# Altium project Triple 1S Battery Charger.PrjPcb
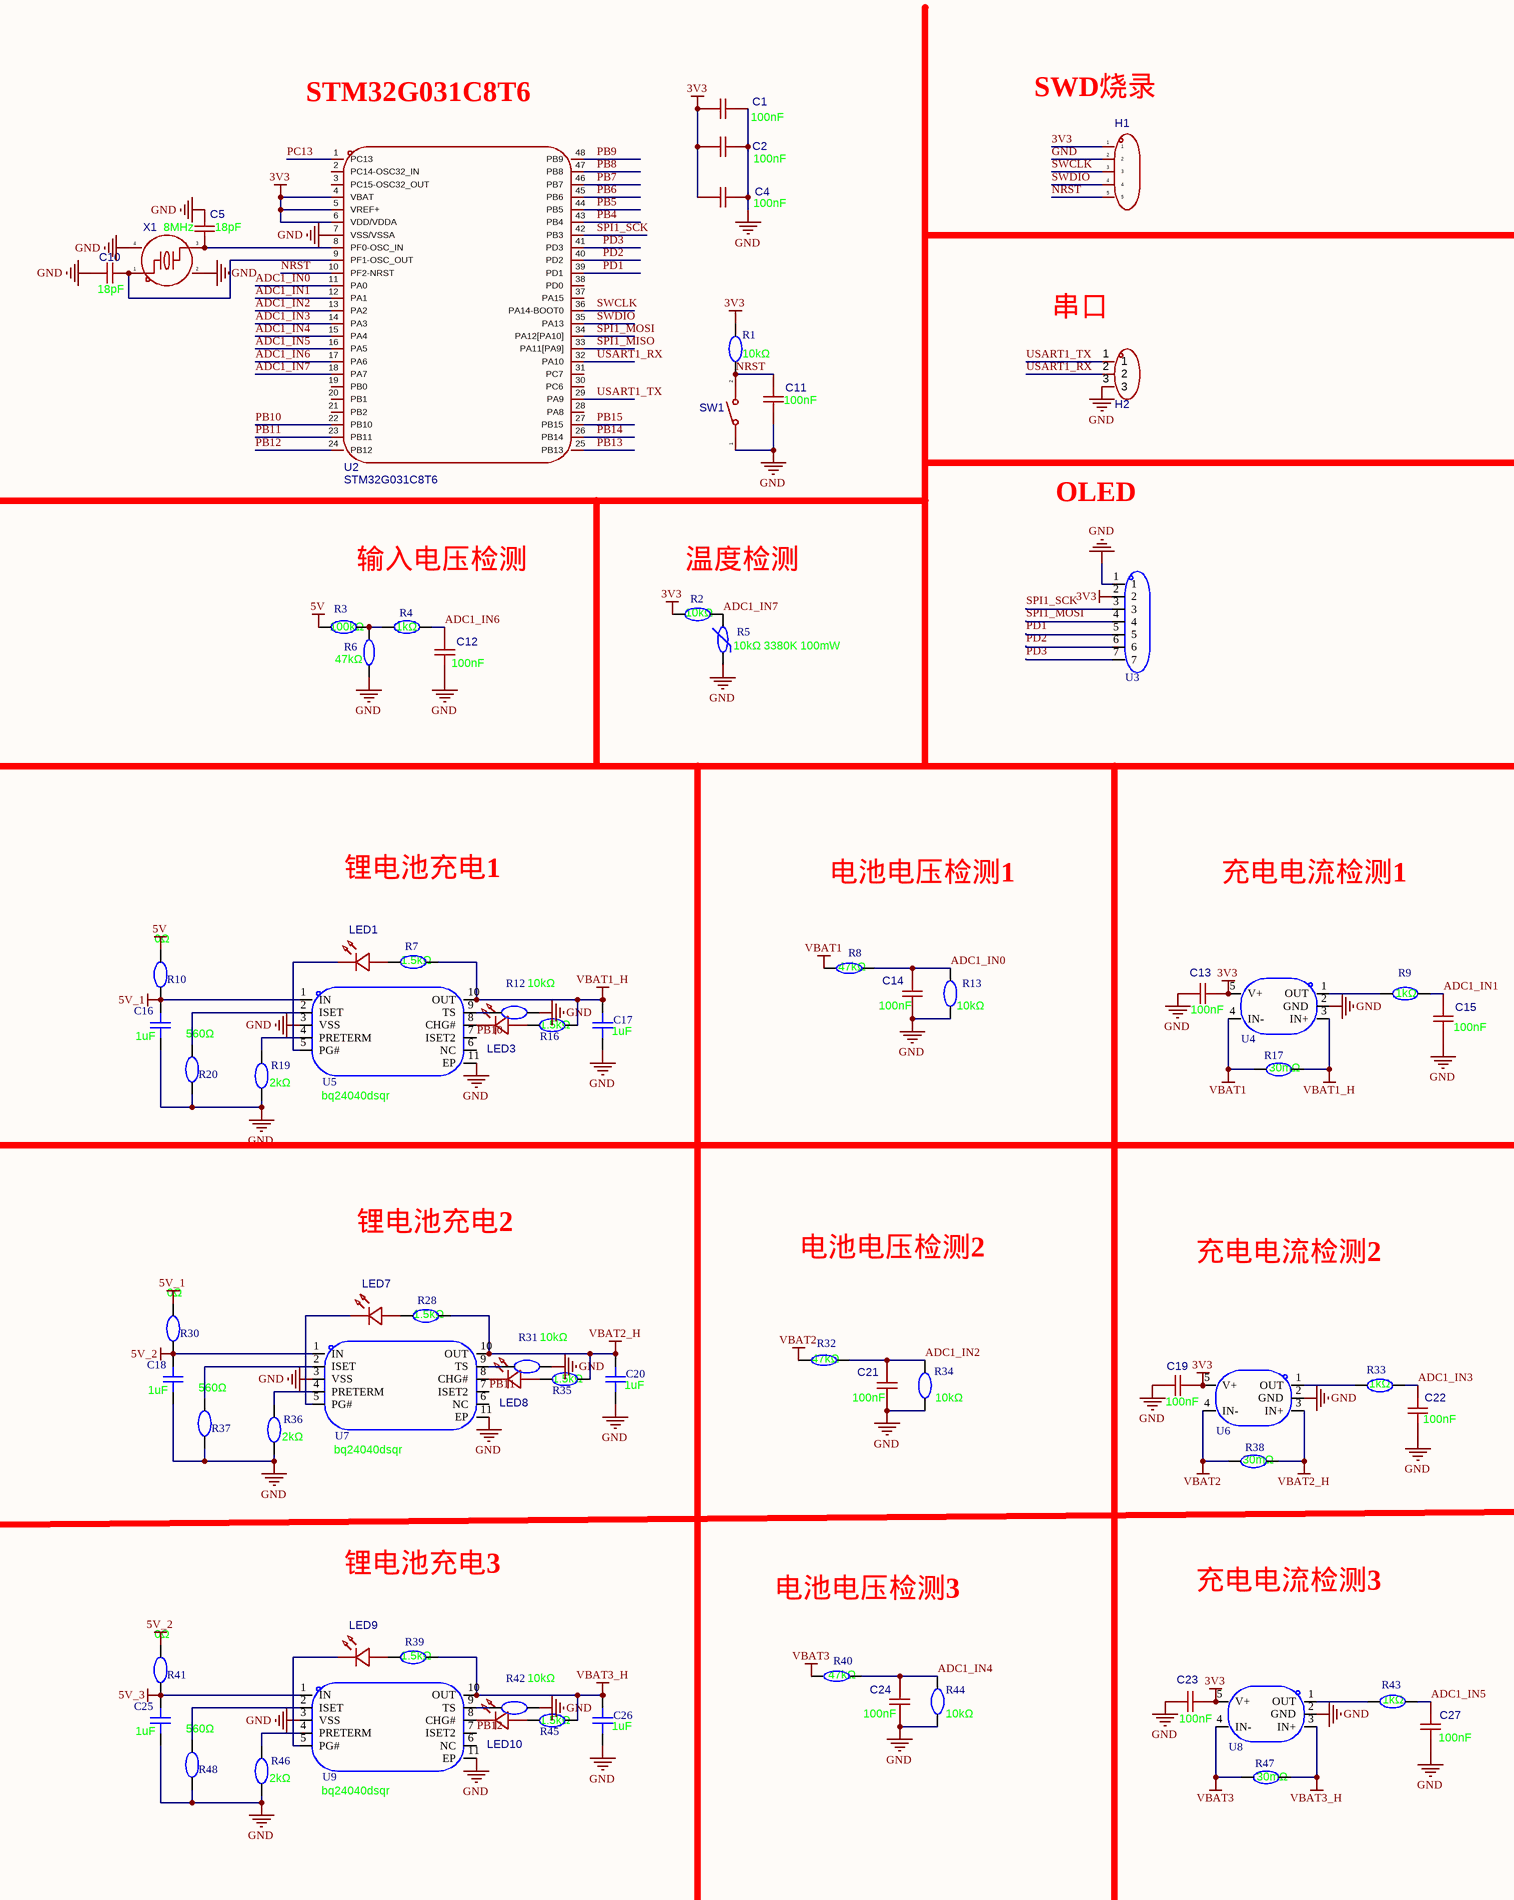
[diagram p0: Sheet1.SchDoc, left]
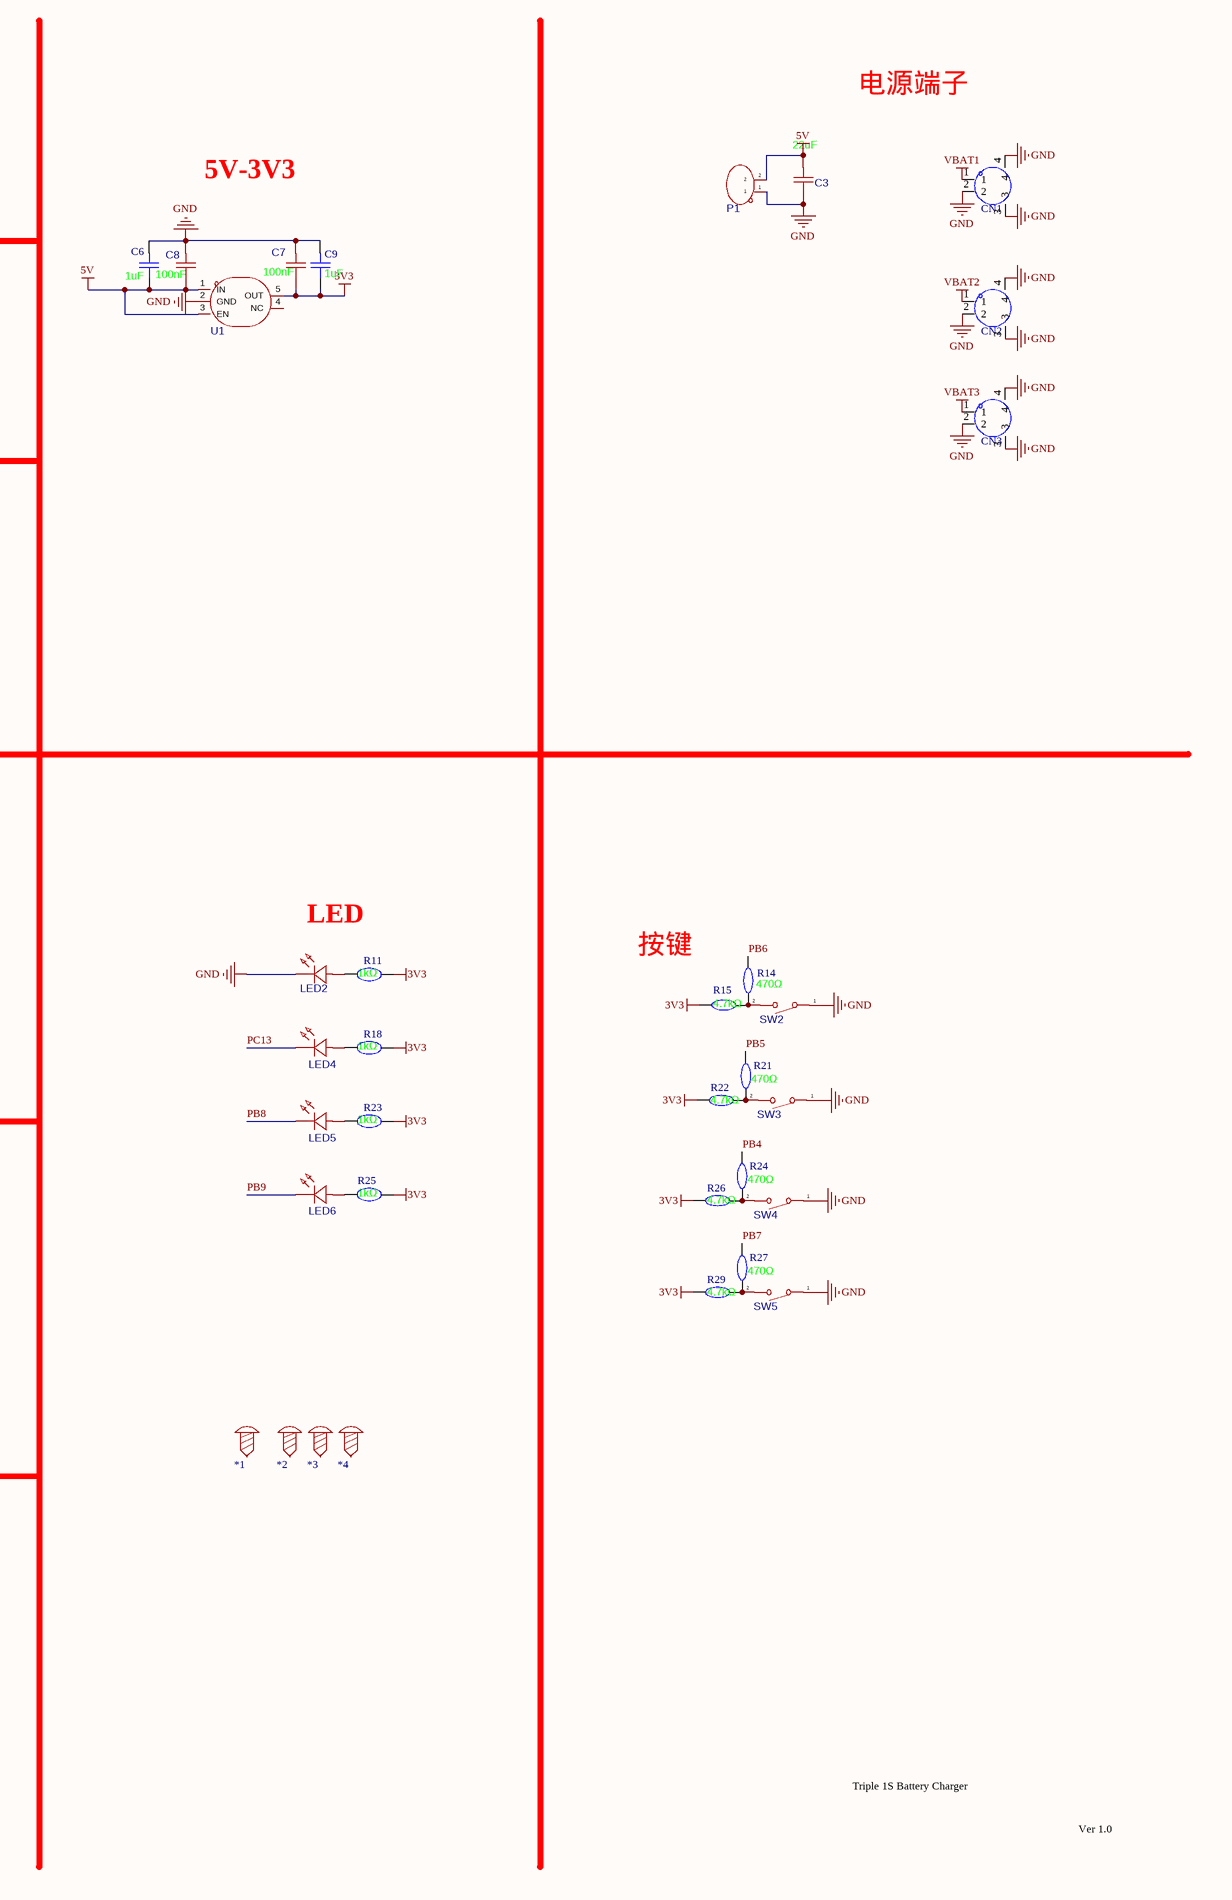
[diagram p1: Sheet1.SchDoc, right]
1 sheet, 110 parts. Net scope: global (net labels, ports and power ports of the same name join across sheets).
Board file: PCB1.PcbDoc

## Sheet Sheet1.SchDoc
size A2; SheetNumber: 1; SheetTotal: 1

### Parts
*1  螺丝孔_1  [M3螺丝]  (value not drawn)
*2  螺丝孔_1  [M3螺丝]  (value not drawn)
*3  螺丝孔_1  [M3螺丝]  (value not drawn)
*4  螺丝孔_1  [M3螺丝]  (value not drawn)
C1  value 100nF  [C0402]  (hidden comment: cc0402krx7r7bb104)
C2  value 100nF  [C0402]  (hidden comment: cc0402krx7r7bb104)
C3  value 22uF  [C0603]  (hidden comment: hgc0603r5226m160nthj)
C4  value 100nF  [C0402]  (hidden comment: cc0402krx7r7bb104)
C5  value 18pF  [C0402]  (hidden comment: cc0402jrnpo9bn180)
C6  value 1uF  [C0402]  (hidden comment: cga0402x5r105k500gt)
C7  value 100nF  [C0402]  (hidden comment: cc0402krx7r7bb104)
C8  value 100nF  [C0402]  (hidden comment: cc0402krx7r7bb104)
C9  value 1uF  [C0402]  (hidden comment: cga0402x5r105k500gt)
C10  value 18pF  [C0402]  (hidden comment: cc0402jrnpo9bn180)
C11  value 100nF  [C0402]  (hidden comment: cc0402krx7r7bb104)
C12  value 100nF  [C0402]  (hidden comment: cc0402krx7r7bb104)
C13  value 100nF  [C0402]  (hidden comment: cc0402krx7r7bb104)
C14  value 100nF  [C0402]  (hidden comment: cc0402krx7r7bb104)
C15  value 100nF  [C0402]  (hidden comment: cc0402krx7r7bb104)
C16  value 1uF  [C0402]  (hidden comment: cga0402x5r105k500gt)
C17  value 1uF  [C0402]  (hidden comment: cga0402x5r105k500gt)
C18  value 1uF  [C0402]  (hidden comment: cga0402x5r105k500gt)
C19  value 100nF  [C0402]  (hidden comment: cc0402krx7r7bb104)
C20  value 1uF  [C0402]  (hidden comment: cga0402x5r105k500gt)
C21  value 100nF  [C0402]  (hidden comment: cc0402krx7r7bb104)
C22  value 100nF  [C0402]  (hidden comment: cc0402krx7r7bb104)
C23  value 100nF  [C0402]  (hidden comment: cc0402krx7r7bb104)
C24  value 100nF  [C0402]  (hidden comment: cc0402krx7r7bb104)
C25  value 1uF  [C0402]  (hidden comment: cga0402x5r105k500gt)
C26  value 1uF  [C0402]  (hidden comment: cga0402x5r105k500gt)
C27  value 100nF  [C0402]  (hidden comment: cc0402krx7r7bb104)
CN1  2.54-2a-lt  [CONN-SMD_2P-P2.54_XH2.54-2AB]  (value not drawn)
CN2  2.54-2a-lt  [CONN-SMD_2P-P2.54_XH2.54-2AB]  (value not drawn)
CN3  2.54-2a-lt  [CONN-SMD_2P-P2.54_XH2.54-2AB]  (value not drawn)
H1  pz254v-11-05p  [HDR-TH_5P-P2.54-V-M]  (value not drawn)
H2  lail-pz2.54-3p-l  [HDR-TH_3P-P2.54-V-M-1]  (value not drawn)
LED1  xl-1005ugc_c965793  [LED0402-RD_GREEN]  (value not drawn)
LED2  xl-1005ugc_c965793  [LED0402-RD_GREEN]  (value not drawn)
LED3  xl-1005ugc_c965793  [LED0402-RD_GREEN]  (value not drawn)
LED4  xl-1005ugc_c965793  [LED0402-RD_GREEN]  (value not drawn)
LED5  xl-1005ugc_c965793  [LED0402-RD_GREEN]  (value not drawn)
LED6  xl-1005ugc_c965793  [LED0402-RD_GREEN]  (value not drawn)
LED7  xl-1005ugc_c965793  [LED0402-RD_GREEN]  (value not drawn)
LED8  xl-1005ugc_c965793  [LED0402-RD_GREEN]  (value not drawn)
LED9  xl-1005ugc_c965793  [LED0402-RD_GREEN]  (value not drawn)
LED10  xl-1005ugc_c965793  [LED0402-RD_GREEN]  (value not drawn)
P1  wj15edgrc-3.81-02p-14-00a  [CONN-TH_2P-P3.81_WJ15EDGRC-3.81-2P]  (value not drawn)
R1  value 10kΩ  [R0402]  (hidden comment: frc0402f1002ts)
R2  value 10kΩ  [R0402]  (hidden comment: frc0402f1002ts)
R3  value 100kΩ  [R0402]  (hidden comment: frc0402f1003ts)
R4  value 1kΩ  [R0402]  (hidden comment: frc0402j102 ts)
R5  LCSC Part Name: 10kΩ 3380K 100mW  [R0402]  (hidden comment: ncp15xh103f03rc)
R6  value 47kΩ  [R0402]  (hidden comment: 0402wgf4702tce)
R7  value 1.5kΩ  [R0402]  (hidden comment: frc0402f1501ts)
R8  value 47kΩ  [R0402]  (hidden comment: 0402wgf4702tce)
R9  value 1kΩ  [R0402]  (hidden comment: frc0402j102 ts)
R10  value 0Ω  [R1206]  (hidden comment: re1206f1r000)
R11  value 1kΩ  [R0402]  (hidden comment: frc0402j102 ts)
R12  value 10kΩ  [R0402]  (hidden comment: frc0402f1002ts)
R13  value 10kΩ  [R0402]  (hidden comment: frc0402f1002ts)
R14  value 470Ω  [R0402]  (hidden comment: 0402wgf4700tce)
R15  value 4.7kΩ  [R0402]  (hidden comment: rc0402fr-074k7l)
R16  value 1.5kΩ  [R0402]  (hidden comment: frc0402f1501ts)
R17  value 30mΩ  [R0805]  (hidden comment: re0805far030)
R18  value 1kΩ  [R0402]  (hidden comment: frc0402j102 ts)
R19  value 2kΩ  [R0402]  (hidden comment: frc0402f2001ts)
R20  value 560Ω  [R0402]  (hidden comment: frc0402f5600ts)
R21  value 470Ω  [R0402]  (hidden comment: 0402wgf4700tce)
R22  value 4.7kΩ  [R0402]  (hidden comment: rc0402fr-074k7l)
R23  value 1kΩ  [R0402]  (hidden comment: frc0402j102 ts)
R24  value 470Ω  [R0402]  (hidden comment: 0402wgf4700tce)
R25  value 1kΩ  [R0402]  (hidden comment: frc0402j102 ts)
R26  value 4.7kΩ  [R0402]  (hidden comment: rc0402fr-074k7l)
R27  value 470Ω  [R0402]  (hidden comment: 0402wgf4700tce)
R28  value 1.5kΩ  [R0402]  (hidden comment: frc0402f1501ts)
R29  value 4.7kΩ  [R0402]  (hidden comment: rc0402fr-074k7l)
R30  value 0Ω  [R1206]  (hidden comment: re1206f1r000)
R31  value 10kΩ  [R0402]  (hidden comment: frc0402f1002ts)
R32  value 47kΩ  [R0402]  (hidden comment: 0402wgf4702tce)
R33  value 1kΩ  [R0402]  (hidden comment: frc0402j102 ts)
R34  value 10kΩ  [R0402]  (hidden comment: frc0402f1002ts)
R35  value 1.5kΩ  [R0402]  (hidden comment: frc0402f1501ts)
R36  value 2kΩ  [R0402]  (hidden comment: frc0402f2001ts)
R37  value 560Ω  [R0402]  (hidden comment: frc0402f5600ts)
R38  value 30mΩ  [R0805]  (hidden comment: re0805far030)
R39  value 1.5kΩ  [R0402]  (hidden comment: frc0402f1501ts)
R40  value 47kΩ  [R0402]  (hidden comment: 0402wgf4702tce)
R41  value 0Ω  [R1206]  (hidden comment: re1206f1r000)
R42  value 10kΩ  [R0402]  (hidden comment: frc0402f1002ts)
R43  value 1kΩ  [R0402]  (hidden comment: frc0402j102 ts)
R44  value 10kΩ  [R0402]  (hidden comment: frc0402f1002ts)
R45  value 1.5kΩ  [R0402]  (hidden comment: frc0402f1501ts)
R46  value 2kΩ  [R0402]  (hidden comment: frc0402f2001ts)
R47  value 30mΩ  [R0805]  (hidden comment: re0805far030)
R48  value 560Ω  [R0402]  (hidden comment: frc0402f5600ts)
SW1  ts-1088-ar02016  [SW-SMD_L3.9-W3.0-P4.45]  (value not drawn)
SW2  ts-1088-ar02016  [SW-SMD_L3.9-W3.0-P4.45]  (value not drawn)
SW3  ts-1088-ar02016  [SW-SMD_L3.9-W3.0-P4.45]  (value not drawn)
SW4  ts-1088-ar02016  [SW-SMD_L3.9-W3.0-P4.45]  (value not drawn)
SW5  ts-1088-ar02016  [SW-SMD_L3.9-W3.0-P4.45]  (value not drawn)
U1  tps7a2033pdbvr  [SOT-23-5_L2.9-W1.6-P0.95-LS2.8-BR]  (value not drawn)
U2  stm32g031c8t6  [LQFP-48_L7.0-W7.0-P0.50-LS9.0-BL]
U3  kh-2.54fh-1x7p-h8.5  [HDR-TH_7P-P2.54-V-F]  (value not drawn)
U4  ina180a3idbvr  [SOT-23-5_L3.0-W1.7-P0.95-LS2.8-BR]  (value not drawn)
U5  bq24040dsqr  [WSON-10_L2.0-W2.0-P0.40-BL-EP]
U6  ina180a3idbvr  [SOT-23-5_L3.0-W1.7-P0.95-LS2.8-BR]  (value not drawn)
U7  bq24040dsqr  [WSON-10_L2.0-W2.0-P0.40-BL-EP]
U8  ina180a3idbvr  [SOT-23-5_L3.0-W1.7-P0.95-LS2.8-BR]  (value not drawn)
U9  bq24040dsqr  [WSON-10_L2.0-W2.0-P0.40-BL-EP]
X1  value 8MHz  [CRYSTAL-SMD_4P-L3.2-W2.5-BL]  (hidden comment: x32258mob4si)

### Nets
3V3: C1.1 C2.1 C4.1 C7.1 C9.1 C13.2 C19.2 C23.2 H1.1 R1.2 R2.1 R11.2 R15.1 R18.2 R22.1 R23.2 R25.2 R26.1 R29.1 U1.5(OUT) U2.4(VBAT) U2.5(VREF+) U2.6(VDD/VDDA) U3.2 U4.5(V+) U6.5(V+) U8.5(V+)
5V: C3.2 C6.1 C8.1 P1.2 R3.1 R10.2 U1.1(IN) U1.3(EN)
5V_1: C16.2 R10.1 R30.2 U5.1(IN)
5V_2: C18.2 R30.1 R41.2 U7.1(IN)
5V_3: C25.2 R41.1 U9.1(IN)
GND: C1.2 C2.2 C3.1 C4.2 C5.2 C6.2 C7.2 C8.2 C9.2 C10.1 C11.1 C12.1 C13.1 C14.2 C15.2 C16.1 C17.1 C18.1 C19.1 C20.1 C21.2 C22.2 C23.1 C24.2 C25.1 C26.1 C27.2 CN1.2 CN1.3 CN1.4 CN2.2 CN2.3 CN2.4 CN3.2 CN3.3 CN3.4 H1.2 H2.3 LED2.1(K) P1.1 R5.1 R6.1 R12.2 R13.2 R19.1 R20.1 R31.2 R34.2 R36.1 R37.1 R42.2 R44.2 R46.1 R48.1 SW1.1 SW2.1 SW3.1 SW4.1 SW5.1 U1.2(GND) U2.7(VSS/VSSA) U3.1 U4.2(GND) U5.3(VSS) U5.11(EP) U6.2(GND) U7.3(VSS) U7.11(EP) U8.2(GND) U9.3(VSS) U9.11(EP) X1.2(GND) X1.4(GND)
VBAT1: CN1.1 R8.1 R17.2 U4.4(IN-)
VBAT1_H: C17.2 R7.2 R16.2 R17.1 U4.3(IN+) U5.10(OUT)
VBAT2: CN2.1 R32.1 R38.2 U6.4(IN-)
VBAT2_H: C20.2 R28.2 R35.2 R38.1 U6.3(IN+) U7.10(OUT)
VBAT3: CN3.1 R40.1 R47.2 U8.4(IN-)
VBAT3_H: C26.2 R39.2 R45.2 R47.1 U8.3(IN+) U9.10(OUT)
ADC1_IN0: C14.1 R8.2 R13.1 U2.11(PA0)
ADC1_IN1: C15.1 R9.2 U2.12(PA1)
ADC1_IN2: C21.1 R32.2 R34.1 U2.13(PA2)
ADC1_IN3: C22.1 R33.2 U2.14(PA3)
ADC1_IN4: C24.1 R40.2 R44.1 U2.15(PA4)
ADC1_IN5: C27.1 R43.2 U2.16(PA5)
ADC1_IN6: C12.2 R4.2 U2.17(PA6)
ADC1_IN7: R2.2 R5.2 U2.18(PA7)
NRST: C11.2 H1.5 R1.1 SW1.2 U2.10(PF2-NRST)
PB4: R24.2 U2.43(PB4)
PB5: R21.2 U2.44(PB5)
PB6: R14.2 U2.45(PB6)
PB7: R27.2 U2.46(PB7)
PB8: LED5.1(K) U2.47(PB8)
PB9: LED6.1(K) U2.48(PB9)
PB10: U2.22(PB10) U5.7(ISET2)
PB11: U2.23(PB11) U7.7(ISET2)
PB12: U2.24(PB12) U9.7(ISET2)
PB13: U2.25(PB13)
PB14: U2.26(PB14)
PB15: U2.27(PB15)
PC13: LED4.1(K) U2.1(PC13)
PD1: U2.39(PD1) U3.5
PD2: U2.40(PD2) U3.6
PD3: U2.41(PD3) U3.7
SPI1_MISO: U2.33(PA11[PA9])
SPI1_MOSI: U2.34(PA12[PA10]) U3.4
SPI1_SCK: U2.42(PB3) U3.3
SWCLK: H1.3 U2.36(PA14-BOOT0)
SWDIO: H1.4 U2.35(PA13)
USART1_RX: H2.2 U2.32(PA10)
USART1_TX: H2.1 U2.29(PA9)
NetC5_1: C5.1 U2.8(PF0-OSC_IN) X1.3
NetC10_2: C10.2 U2.9(PF1-OSC_OUT) X1.1
NetLED1_1: LED1.1(K) U5.5(PG#)
NetLED1_2: LED1.2(A) R7.1
NetLED2_2: LED2.2(A) R11.1
NetLED3_1: LED3.1(K) U5.8(CHG#)
NetLED3_2: LED3.2(A) R16.1
NetLED4_2: LED4.2(A) R18.1
NetLED5_2: LED5.2(A) R23.1
NetLED6_2: LED6.2(A) R25.1
NetLED7_1: LED7.1(K) U7.5(PG#)
NetLED7_2: LED7.2(A) R28.1
NetLED8_1: LED8.1(K) U7.8(CHG#)
NetLED8_2: LED8.2(A) R35.1
NetLED9_1: LED9.1(K) U9.5(PG#)
NetLED9_2: LED9.2(A) R39.1
NetLED10_1: LED10.1(K) U9.8(CHG#)
NetLED10_2: LED10.2(A) R45.1
NetR3_2: R3.2 R4.1 R6.2
NetR9_1: R9.1 U4.1(OUT)
NetR12_1: R12.1 U5.9(TS)
NetR14_1: R14.1 R15.2 SW2.2
NetR19_2: R19.2 U5.4(PRETERM)
NetR20_2: R20.2 U5.2(ISET)
NetR21_1: R21.1 R22.2 SW3.2
NetR24_1: R24.1 R26.2 SW4.2
NetR27_1: R27.1 R29.2 SW5.2
NetR31_1: R31.1 U7.9(TS)
NetR33_1: R33.1 U6.1(OUT)
NetR36_2: R36.2 U7.4(PRETERM)
NetR37_2: R37.2 U7.2(ISET)
NetR42_1: R42.1 U9.9(TS)
NetR43_1: R43.1 U8.1(OUT)
NetR46_2: R46.2 U9.4(PRETERM)
NetR48_2: R48.2 U9.2(ISET)

Not connected (* = marked no-connect by the designer): *1 1; *2 1; *3 1; *4 1; U1 4(NC); U2 2(PC14-OSC32_IN) 3(PC15-OSC32_OUT) 19(PB0) 20(PB1) 21(PB2) 28(PA8) 30(PC6) 31(PC7) 37(PA15) 38(PD0); U5 6(NC); U7 6(NC); U9 6(NC)

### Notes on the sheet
- 电源端子
- STM32G031C8T6
- (near H1) SWD烧录
- 5V-3V3
- 串口
- OLED
- 输入电压检测
- 温度检测
- 锂电池充电1
- 电池电压检测1
- 充电电流检测1
- LED
- 按键
- 锂电池充电2
- 电池电压检测2
- 充电电流检测2
- 锂电池充电3
- 电池电压检测3
- 充电电流检测3
- Triple 1S Battery Charger
- Ver 1.0

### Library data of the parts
C1 C2 C4 C7 C8 C11-C15 C19 C21-C24 C27 = cc0402krx7r7bb104: 容值:100nF;精度:±10%;额定电压:16V;温度系数:X7R;; Manufacturer: YAGEO(国巨); AddInBom: yes; ModelId: 36a51122f27c49738f86b3bfa98863e0; ModelName: C0402_L1.0-W0.5-H0.5; ModelTransform: 39.37,19.685,0,0,0,0,0,0,0; Tolerance: ±10%; Voltage Rating: 16V; Temperature Coefficient: X7R
C3 = hgc0603r5226m160nthj: 容值:22uF;精度:±20%;额定电压:16V;温度系数:X5R;; Manufacturer: Chinocera(华瓷); AddInBom: yes; ModelId: ac125912035d415993ca9572d50418b1; ModelName: C0603_L1.6-W0.8-H0.8; ModelTransform: 62.992,31.496,0,0,0,0,0,0,0; Tolerance: ±20%; Voltage Rating: 16V; Temperature Coefficient: X5R
C5 C10 = cc0402jrnpo9bn180: 容值:18pF;精度:±5%;额定电压:50V;温度系数:NP0;; Manufacturer: YAGEO(国巨); AddInBom: yes; ModelId: 36a51122f27c49738f86b3bfa98863e0; ModelName: C0402_L1.0-W0.5-H0.5; ModelTransform: 39.37,19.685,0,0,0,0,0,0,0; Tolerance: ±5%; Voltage Rating: 50V; Temperature Coefficient: NP0
C6 C9 C16-C18 C20 C25 C26 = cga0402x5r105k500gt: 容值:1uF;精度:±10%;额定电压:50V;温度系数:X5R;; Manufacturer: HRE(芯声); AddInBom: yes; ModelId: 36a51122f27c49738f86b3bfa98863e0; ModelName: C0402_L1.0-W0.5-H0.5; ModelTransform: 39.37,19.685,0,0,0,0,0,0,0; Tolerance: ±10%; Voltage Rating: 50V; Temperature Coefficient: X5R
CN1-CN3 = 2.54-2a-lt: 插针结构:1x2P;间距:2.54mm;安装方式:立贴;参考系列:XH;总PIN数:2P;排数:1;每排PIN数:2;行距:-;额定电流:500mA;触头材质:磷铜;触头镀层:锡;工作温度:-25℃~+85℃;; Manufacturer: CAX(创都); AddInBom: yes; ModelId: d8a33bf5c0154e0995c08ba39c3c8f35; ModelName: CONN-SMD_XH2.54-LS-2P; ModelTransform: 393.7,354.33,0,0,0,0,0,9.843,0; Pins Structure: 1x2P; Pitch: 2.54mm; Reference Series: XH; Number of PINs Per Row: 2; Current Rating: 500mA; Voltage Rating: 50V; Plastic Material: LCP; Z-Height of the Board: 7.9mm; Y-Width of Bottom Edge on Board: 6mm
H1 = pz254v-11-05p: 插针结构:1x5P;间距:2.54mm;行距:-;圆针/方针:方针;安装方式:直插;排数:单排;总PIN位数:5P;额定电流:3A;额定电压:250V;配合针长度:6mm;塑高:2.5mm;端接针长度:3mm;触头材质:黄铜;触头镀层:-;工作温度:-40℃~+105℃;颜色:黑色;; Manufacturer: XFCN(兴飞); AddInBom: yes; ModelId: 47d466e4a34f4fc5bc626cf773a24dd5; ModelName: HDR-TH_5P-P2.54-M-LI-1X5P; ModelTransform: 499.999,100,0,0,0,0,0,0,-118.11; Pin Structure: 1x5P; Pitch: 2.54mm; Circluar Pins/Square Pins: 方针; Current Rating: 3A; Voltage Rating (Max): 250V
H2 = lail-pz2.54-3p-l: 插针结构:1x3P;间距:2.54mm;圆针/方针:方针;排数:单排;总PIN位数:3P;额定电流:3A;额定电压:250V;塑高:2.5mm;端接针长度:3mm;触头材质:黄铜;触头镀层:金;工作温度:-25℃~+80℃;颜色:黑色;; Manufacturer: LAILAN(莱联); AddInBom: yes; ModelId: 94a8ffe137b6410295cb18cd3ffd99db; ModelName: HDR-M-2.54_1x3; ModelTransform: 299.9994,100,0,0,0,0,0,0,-118.11; Pin Structure: 1x3P; Pitch: 2.54mm; Circluar Pins/Square Pins: 方针; Current Rating: 3A; Voltage Rating (Max): 250V
LED1-LED10 = xl-1005ugc_c965793: 灯头类型:1.0mmx0.5mm方形灯头;发光颜色:翠绿色;正向压降(Vf):3V;功率:80mW;正向电流:25mA;波长:516nm~531nm;二极管配置:独立二极管;透镜颜色:无色透明透镜;色温:-;发光强度:249mcd;发光角度:120°;载带方式:正贴;工作温度:-40℃~+85℃;; Manufacturer: XINGLIGHT(成兴光); AddInBom: yes; ModelId: 080bb9bd520f4b34ac21e218e7b036d6; ModelName: LED0402_L1.0-W0.5-H0.2; ModelTransform: 40.1574,19.685,0,0,0,0,0,-0.0005,0; Illumination Color: 翠绿色; Voltage - Forward(Vf): 3V; Power(Watts): 80mW; Forward Current: 25mA; Peak Wavelength: 531nm; Diode Configuration: 独立二极管; Lens Color: 无色透明透镜; Luminous Intensity: 249mcd; Viewing Angle: 120°
P1 = wj15edgrc-3.81-02p-14-00a: 连接器类型:板端/插座-闭口;固定方式:无固定装置;结构:1x2P;间距:3.81mm;颜色:绿色;安装方式:弯插;排数:1;每排PIN数:2;额定电流:8A;额定电压:300V;线规 - AWG:-;线规 - 平方毫米:-;工作温度:-40℃~+105℃;; Manufacturer: KANGNEX(康奈克斯电气); Symbol: WJ15EDGRC-3.81-2P; AddInBom: yes; ModelId: 816ec8aca6fe4785be70cb4c5121258d; ModelName: CONN-TH_2P_L8.5-W9.2-H7.0-P3.81; ModelTransform: 334.645,360.2355,0,0,0,0,0,-118.11,-137.795; Number of Positions or Pins: 1x2P; Pitch: 3.81mm; Number of PINs Per Row: 2; Current Rating: 8A; Voltage Rating (Max): 300V
R1 R2 R12 R13 R31 R34 R42 R44 = frc0402f1002ts: 电阻类型:厚膜电阻;阻值:10kΩ;精度:±1%;功率:62.5mW;工作电压:50V;温度系数:±100ppm/℃;; Manufacturer: FOJAN(富捷); AddInBom: yes; ModelId: 98c88bc2b9094f218f3a3e30a7012738; ModelName: R0402_L1.0-W0.5-H0.4; ModelTransform: 39.37,19.685,0,0,0,0,0,0,0; Tolerance: ±1%; Power(Watts): 62.5mW; Voltage-Supply(Max): 50V
R3 = frc0402f1003ts: 电阻类型:厚膜电阻;阻值:100kΩ;精度:±1%;功率:62.5mW;工作电压:50V;温度系数:±100ppm/℃;; Manufacturer: FOJAN(富捷); AddInBom: yes; ModelId: 98c88bc2b9094f218f3a3e30a7012738; ModelName: R0402_L1.0-W0.5-H0.4; ModelTransform: 39.37,19.685,0,0,0,0,0,0,0; Tolerance: ±1%; Power(Watts): 62.5mW; Voltage-Supply(Max): 50V
R4 R9 R11 R18 R23 R25 R33 R43 = frc0402j102 ts: 电阻类型:厚膜电阻;阻值:1kΩ;精度:±5%;功率:62.5mW;工作电压:50V;温度系数:±100ppm/℃;; Manufacturer: FOJAN(富捷); AddInBom: yes; ModelId: 98c88bc2b9094f218f3a3e30a7012738; ModelName: R0402_L1.0-W0.5-H0.4; ModelTransform: 39.37,19.685,0,0,0,0,0,0,0; Tolerance: ±5%; Power(Watts): 62.5mW; Voltage-Supply(Max): 50V
R5 = ncp15xh103f03rc: 阻值:10kΩ;B值(25℃/50℃):3380K;电阻精度:±1%;功率:100mW;B值精度:±1%;最大稳态电流(25℃):310uA;; Manufacturer: muRata(村田); AddInBom: yes; ModelId: 98c88bc2b9094f218f3a3e30a7012738; ModelName: R0402_L1.0-W0.5-H0.4; ModelTransform: 39.37,19.685,0,0,0,0,0,0,0; Resistance @ 25℃: 10kΩ; B Constant (25℃/50℃): 3380K; Resistance Tolerance: ±1%; B Constant (25℃/85℃): 3434K; B Constant (25℃/100℃): 3455K; Power(Watts): 100mW; Steady State Current (Max): 310uA; Dissipation Factor: 1mW/℃
R6 R8 R32 R40 = 0402wgf4702tce: 电阻类型:厚膜电阻;阻值:47kΩ;精度:±1%;功率:62.5mW;工作电压:50V;温度系数:±100ppm/℃;; Manufacturer: UNI-ROYAL(厚声); AddInBom: yes; ModelId: 98c88bc2b9094f218f3a3e30a7012738; ModelName: R0402_L1.0-W0.5-H0.4; ModelTransform: 39.37,19.685,0,0,0,0,0,0,0; Tolerance: ±1%; Power(Watts): 62.5mW; Voltage-Supply(Max): 50V
R7 R16 R28 R35 R39 R45 = frc0402f1501ts: 电阻类型:厚膜电阻;阻值:1.5kΩ;精度:±1%;功率:62.5mW;工作电压:50V;温度系数:±100ppm/℃;; Manufacturer: FOJAN(富捷); AddInBom: yes; ModelId: 98c88bc2b9094f218f3a3e30a7012738; ModelName: R0402_L1.0-W0.5-H0.4; ModelTransform: 39.37,19.685,0,0,0,0,0,0,0; Tolerance: ±1%; Power(Watts): 62.5mW; Voltage-Supply(Max): 50V
R10 R30 R41 = re1206f1r000: 电阻类型:采样电阻；合金电阻;阻值:0Ω;精度:±1%;功率:1W;安装方式:贴片;; Manufacturer: JIERR(捷而瑞); AddInBom: yes; ModelId: 89a1f13db2384da588040e0b3c55bf66; ModelName: R1206_L3.2-W1.6-H0.6; ModelTransform: 125.984,62.992,0,0,0,0,0,0,0; Tolerance: ±1%; Power(Watts): 1W
R14 R21 R24 R27 = 0402wgf4700tce: 电阻类型:厚膜电阻;阻值:470Ω;精度:±1%;功率:62.5mW;工作电压:50V;温度系数:±100ppm/℃;; Manufacturer: UNI-ROYAL(厚声); AddInBom: yes; ModelId: 98c88bc2b9094f218f3a3e30a7012738; ModelName: R0402_L1.0-W0.5-H0.4; ModelTransform: 39.37,19.685,0,0,0,0,0,0,0; Tolerance: ±1%; Power(Watts): 62.5mW; Voltage-Supply(Max): 50V
R15 R22 R26 R29 = rc0402fr-074k7l: 电阻类型:厚膜电阻;阻值:4.7kΩ;精度:±1%;功率:62.5mW;工作电压:50V;温度系数:±100ppm/℃;; Manufacturer: YAGEO(国巨); AddInBom: yes; ModelId: 98c88bc2b9094f218f3a3e30a7012738; ModelName: R0402_L1.0-W0.5-H0.4; ModelTransform: 39.37,19.685,0,0,0,0,0,0,0; Tolerance: ±1%; Power(Watts): 62.5mW; Voltage-Supply(Max): 50V
R17 R38 R47 = re0805far030: 电阻类型:合金电阻;阻值:30mΩ;精度:±1%;功率:500mW;温度系数:±50ppm/℃;安装方式:贴片;; Manufacturer: JIERR(捷而瑞); AddInBom: yes; ModelId: 37a81e68749a4138bd2dfa6897b24b85; ModelName: R0805_L2.0-W1.3-H0.6; ModelTransform: 78.74,51.181,0,0,0,0,0,-0.0005,0; Tolerance: ±1%; Power(Watts): 500mW
R19 R36 R46 = frc0402f2001ts: 电阻类型:厚膜电阻;阻值:2kΩ;精度:±1%;功率:62.5mW;工作电压:50V;温度系数:±100ppm/℃;; Manufacturer: FOJAN(富捷); AddInBom: yes; ModelId: 98c88bc2b9094f218f3a3e30a7012738; ModelName: R0402_L1.0-W0.5-H0.4; ModelTransform: 39.37,19.685,0,0,0,0,0,0,0; Tolerance: ±1%; Power(Watts): 62.5mW; Voltage-Supply(Max): 50V
R20 R37 R48 = frc0402f5600ts: 电阻类型:厚膜电阻;阻值:560Ω;精度:±1%;功率:62.5mW;工作电压:50V;温度系数:±100ppm/℃;; Manufacturer: FOJAN(富捷); AddInBom: yes; ModelId: 98c88bc2b9094f218f3a3e30a7012738; ModelName: R0402_L1.0-W0.5-H0.4; ModelTransform: 39.37,19.685,0,0,0,0,0,0,0; Tolerance: ±1%; Power(Watts): 62.5mW; Voltage-Supply(Max): 50V
SW1-SW5 = ts-1088-ar02016: 电路结构:单刀单掷;按钮形状:圆形按钮;作用力:1.6N;安装方式:立贴;开关长度:3.9mm;开关宽度:3mm;开关高度:2mm;带支架:不带支架;触点电流:50mA;额定电压:12V;带灯:-;工作寿命:10万次;; Manufacturer: XUNPU(讯普); AddInBom: yes; ModelId: b26698b69f274ffabef8a26c7d0e5dd1; ModelName: SW-SMD_L3.9-W2.9-H2.0-LS4.8; ModelTransform: 188.976,114.174,0,0,0,0,0,0,0; Circuit: 单刀单掷; Actuator Style: 圆形按钮; Operating Force: 1.6N; Switch Height: 2mm; with Bracket: 不带支架; Contact Current: 50mA; Voltage Rating: 12V; Actuator/Cap Color: 黑色; Life: 10万次
U1 = tps7a2033pdbvr: 输出类型:固定;最大输入电压:6V;输出电压:3.3V;输出电流:300mA;输出极性:正极;; Manufacturer: TI(德州仪器); AddInBom: yes; ModelId: 7ba65df16e7b4570af156e925f9c37fe; ModelTransform: 114.173,114.173,0,90,0,0,0,0,0; Output Type: 固定; Maximum Input Voltage: 6V; Output Voltage: 3.3V; Output Current: 300mA; Dropout Voltage: 140mV@(300mA); standby current: 15uA; Output Polarity: 正极; Number of Outputs: 1
U2 = stm32g031c8t6: CPU内核:ARM Cortex-M0+;CPU最大主频:64MHz;CPU位数:32 Bit;; Manufacturer: ST(意法半导体); AddInBom: yes; ModelId: 093be70396ff421eb2cdb946d5311efc; ModelName: LQFP-48_L7.0-W7.0-H1.4-LS9.0-P0.50; ModelTransform: 354.331,354.331,0,0,0,0,0,0,0; CPU Maximum Speed: 64MHz; Core Size: 32 Bit; Program Storage Size: 64KB; Program Memory Type: FLASH; RAM Size: 8KB; Number of I/O: 44; ADC (Bit): 12bit; Oscillator Type: 内置+外置; Voltage - Supply: 1.7V~3.6V
U3 = kh-2.54fh-1x7p-h8.5: 插孔结构:1x7P;间距:2.54mm;行距:-;圆孔/方孔:方孔;安装方式:直插;排数:单排;总孔位数:7P;额定电流:3A;额定电压:-;插孔方向:顶部;塑高:8.5mm;工作温度:-40℃~+105℃;; Manufacturer: kinghelm(金航标); AddInBom: yes; ModelId: 4c31987253bc43b9b52c17be2a6d3f91; ModelName: HDR-TH_7P-P2.54-F-LI-1X7P; ModelTransform: 715.7466,94.488,0,0,0,0,0,0,-118.11; Holes Structure: 1x7P; Pitch: 2.54mm; Circular Hole / Square Hole: 方孔; Number of Positions: 7P; Current Rating: 3A; Holes Direction: 顶部
U4 U6 U8 = ina180a3idbvr: 放大器数:1;共模电压:-200mV~26V;增益:100V/V;带宽(-3db):150kHz;; Manufacturer: TI(德州仪器); AddInBom: yes; ModelId: 0a2a1b8f50944f73965918ad6e5fe167; ModelName: SOT-23-5_L2.9-W1.6-H1.1-LS2.8-P0.95; ModelTransform: 114.173,109.636,0,180,0,0,0,0,0; Number of Channels: 1; Gain: 100V/V; Bandwidth: 150kHz; Ib - Input Bias Current: 100nA; Vos - Input Offset Voltage: 25uV; Differential Voltage: ±26V; Single Supply: 2.7V~5.5V; Quiescent Current: 197uA; Output Current: 8mA; Input Offset Voltage Drift(Vos TC): 1uV/℃; Slew Rate: 2V/us; Common Mode Rejection Ratio (CMRR): 100dB; Noise density(eN): 40nV/√Hz@1kHz
U5 U7 U9 = bq24040dsqr: 工作电压:3.5V~28V;最大充电电流:1A;电池类型:锂电池;电池节数:1;; Manufacturer: TI(德州仪器); AddInBom: yes; ModelId: 0e1275d2e7d54e69a402a354e9203fe9; ModelName: WSON-10_L2.0-W2.0-H0.8-P0.40; ModelTransform: 78.74,79.527,0,0,0,0,0,0,0; The Chip Type: 充电芯片; Charge Current - Max: 1A; Charging Saturation Voltage: 4.2V; End-Off Voltage: 800mV; Type of Battery: 锂电池; Number of Cells: 1; Battery Temperature Detection: 支持; Supply Current (Iq): 1mA
X1 = x32258mob4si: 晶振类型:贴片晶振;频率:8MHz;常温频差:±10ppm;负载电容:12pF;频率稳定度:±20ppm;; Manufacturer: YXC(扬兴晶振); AddInBom: yes; ModelId: ff2dfd5650294453a14147960efe1838; ModelTransform: 125.984,98.425,0,0,0,0,0,0,0; Normal temperature Frequency Tolerance: ±10ppm; Load Capacitance: 12pF; Frequency Stability: ±20ppm; Equivalent Series Resistance(ESR): 180Ω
